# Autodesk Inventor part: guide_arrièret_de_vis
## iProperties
Shininess: 64.0
Length Units: 11269
Angle Units: 11279
Time Units: 11290
Mass Units: 11283
Length Display Precision: 3
Angle Display Precision: 2
Compacted: True
Part Number: guide_arrièret_de_vis
Document SubType Name: Modeling
Created: 2004-05
Material: Par défaut
Designer: David
Density: 0.0
Volumn: 0.0
Area: 0.0
PropertySet Name: Model Information
Control State: 0
Master: False
Checked Out: False
Author: David
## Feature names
1. Révolution1 [Revolution]
